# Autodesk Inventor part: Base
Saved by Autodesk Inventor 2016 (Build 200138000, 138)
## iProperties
Created: 2016-03
Part Number: Base
Material: Generic
Document SubType Name: Modeling
Designer: bongo_000
Density: 1 g/cm^3
Appearance: Default
Author: bongo_000
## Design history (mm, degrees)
feature "SOLID1"
body "Solid1"
